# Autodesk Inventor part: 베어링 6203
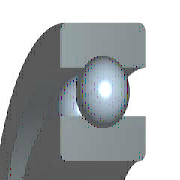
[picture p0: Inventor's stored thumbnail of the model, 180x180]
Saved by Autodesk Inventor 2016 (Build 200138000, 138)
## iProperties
IsCustomPart: 0
Company: 한국ATC센터
Created: 2015-11
Part Number: 베어링 6203
Material: 강철, 연강
Description: 깊은 그루브 볼 베어링
Document SubType Name: Modeling
Standard: KS B 2023
Designer: mdu
Standards Organization: KS
Language: ko-KR
Size Designation: 6203 - 17 x 40 x 12
Categories: <MemberInstance><Categories><Category DisplayName="샤프트 부품" InternalName="7f7aeb1f-a693-4053-b835-cee3144e0d98" Mnemonic="SHFT"><Category DisplayName="베어링" Inter
Density: 7.86 g/cm^3
Appearance: 크롬 - 광택
Mass: 64.9809 g
Surface Area: 64.3582 cm^2
Volume: 8.26729 cm^3
Author: mdu
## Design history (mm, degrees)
sketch "스케치" dims "d0" = 5.98 (= -0.26 x WD + 0.26 x BD)
  geometry: L1 (3.01, 14.25)-(8.99, 14.25); L2 (6, 14.25)-(6, 11.26); L3 (6, 14.25)-(6, 17.24); L4 (3.778, 12.249)-(0, 12.249); L5 (0, 8.5)-(12, 8.5); L6 (3.778, 16.251)-(0, 16.251); L7 (0, 20)-(12, 20); L8 (12, 8.5)-(12, 12.249); L9 (8.222, 12.249)-(12, 12.249); L10 (8.222, 16.251)-(12, 16.251); L11 (12, 20)-(12, 16.251); L12 (-1.4, 0)-(8.4, 0) reference; L13 (0, -0.3)-(0, 5.3) reference
  constraints: 22 end point, 4 point on line, 2 collinear, 2 perpendicular, 2 symmetric about line, 1 midpoint, 1 parallel, 14 other
  dimensions: "d9" = 17 diameter of L5 L12 (= WD); "d11" = 40 diameter of L7 L12 (= BD); "d12" = 12 distance between parallel lines of L8 L13 (= KB); "d13" = 24.498 diameter of L9 L12 (= 0.326 x BD + 0.674 x WD)
revolve "본체" stored, may be unused: angle "d6" = 90 deg
revolve "볼" stored, may be unused: angle "d7" = 90 deg
pattern_circular "IDS_ARRAYBALL[SIMPL:T]" dims angle "d3" = 360 deg
body "Solid1"
fillet "모깎기1" dims "d1" = 0.6 (= KRS)
other parameters: "WD" = 17 [user parameter; used in 5 equation terms], "BD" = 40 [user parameter; used in 5 equation terms], "KB" = 12 [user parameter; used in 1 equation term], "KRS" = 0.6 [user parameter; used in 1 equation term], "d4" = 0, "d5" = 0, "d8" = 0, "d14" = 0, "d15" = 0, "BBA" = 0 [user parameter], "BC0" = 4750000 [user parameter], "BC" = 9560000 [user parameter], "WR" = 8.5 (= 0.5 x WD) [user parameter]
